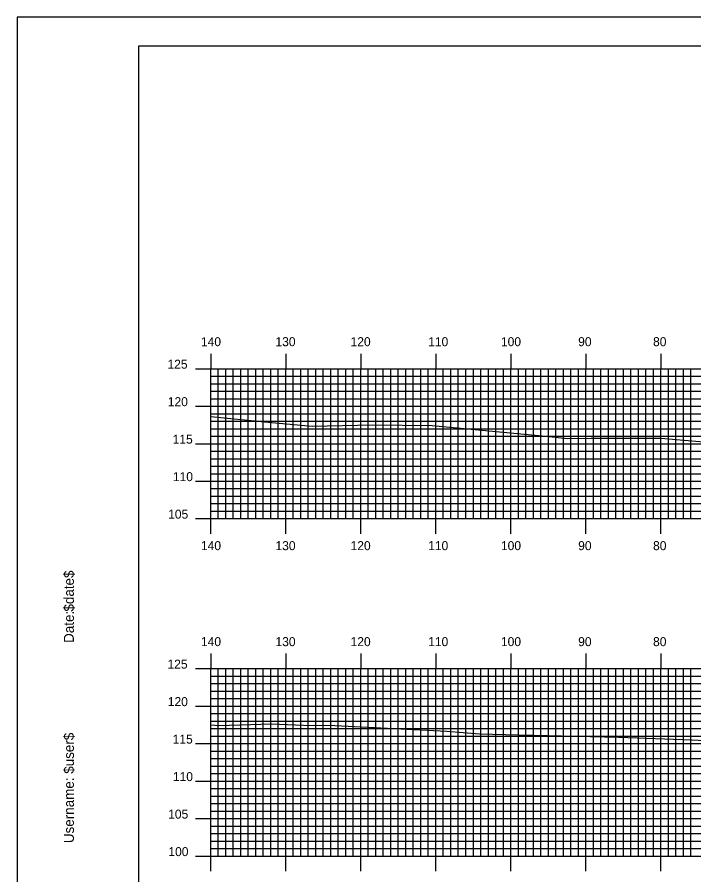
# Model space of a CAD drawing. Extents: x 1779893 to 1780236, y 442591 to 442811.
# Drawn here: x 1779892.6 to 1779982.7, y 442696.2 to 442810.5 of the extents above; entities that cross this region are included whole.
import ezdxf

# ---------------------------------------------------------------- set-up
doc = ezdxf.new("R2010")
doc.units = 0
for name, color, linetype in [('BORDER', 7, 'Continuous'), ('H_V ANNOTATION', 7, 'Continuous'), ('MAJOR', 7, 'Continuous'), ('MINOR', 7, 'Continuous'), ('PLOT BOUNDARY', 7, 'Continuous'), ('S_Roadway_Centerline', 7, 'Continuous')]:
    doc.layers.add(name, color=color, linetype=linetype)

msp = doc.modelspace()

# ---------------------------------------------------------------- linework, layer by layer
at = {"layer": 'BORDER'}
msp.add_lwpolyline([(1779908.76, 442596.67), (1780228.76, 442596.67), (1780228.76, 442806.67), (1779908.76, 442806.67)], close=True, dxfattribs=at)
at = {"layer": 'MAJOR'}
for p, q in [((1779918.36, 442765.67), (1779918.36, 442763.67)), ((1779928.36, 442765.67), (1779928.36, 442763.67)), ((1779938.36, 442765.67), (1779938.36, 442763.67)), ((1779948.36, 442765.67), (1779948.36, 442763.67)), ((1779958.36, 442765.67), (1779958.36, 442763.67)), ((1779968.36, 442765.67), (1779968.36, 442763.67)), ((1779978.36, 442765.67), (1779978.36, 442763.67)), ((1779916.35, 442763.67), (1779918.36, 442763.67)), ((1779918.36, 442763.67), (1780198.36, 442763.67)), ((1779918.36, 442743.67), (1779918.36, 442763.67)), ((1779918.36, 442743.67), (1779918.36, 442763.67)), ((1779918.36, 442763.67), (1780198.36, 442763.67)), ((1779928.36, 442743.67), (1779928.36, 442763.67)), ((1779938.36, 442743.67), (1779938.36, 442763.67)), ((1779948.36, 442743.67), (1779948.36, 442763.67)), ((1779958.36, 442743.67), (1779958.36, 442763.67)), ((1779968.36, 442743.67), (1779968.36, 442763.67)), ((1779978.36, 442743.67), (1779978.36, 442763.67)), ((1779916.35, 442758.67), (1779918.36, 442758.67)), ((1779918.36, 442758.67), (1780198.36, 442758.67)), ((1779916.35, 442753.67), (1779918.36, 442753.67)), ((1779918.36, 442753.67), (1780198.36, 442753.67)), ((1779916.35, 442748.67), (1779918.36, 442748.67)), ((1779918.36, 442748.67), (1780198.36, 442748.67)), ((1779916.35, 442743.67), (1779918.36, 442743.67)), ((1779918.36, 442743.67), (1780198.36, 442743.67)), ((1779918.36, 442743.67), (1780198.36, 442743.67)), ((1779918.36, 442741.66), (1779918.36, 442743.67)), ((1779928.36, 442741.66), (1779928.36, 442743.67)), ((1779938.36, 442741.66), (1779938.36, 442743.67)), ((1779948.36, 442741.66), (1779948.36, 442743.67)), ((1779958.36, 442741.66), (1779958.36, 442743.67)), ((1779968.36, 442741.66), (1779968.36, 442743.67)), ((1779978.36, 442741.66), (1779978.36, 442743.67)), ((1779918.36, 442725.67), (1779918.36, 442723.67)), ((1779928.36, 442725.67), (1779928.36, 442723.67)), ((1779938.36, 442725.67), (1779938.36, 442723.67)), ((1779948.36, 442725.67), (1779948.36, 442723.67)), ((1779958.36, 442725.67), (1779958.36, 442723.67)), ((1779968.36, 442725.67), (1779968.36, 442723.67)), ((1779978.36, 442725.67), (1779978.36, 442723.67)), ((1779916.35, 442723.67), (1779918.36, 442723.67)), ((1779918.36, 442723.67), (1780198.36, 442723.67)), ((1779918.36, 442698.67), (1779918.36, 442723.67)), ((1779918.36, 442698.67), (1779918.36, 442723.67)), ((1779918.36, 442723.67), (1780198.36, 442723.67)), ((1779928.36, 442698.67), (1779928.36, 442723.67)), ((1779938.36, 442698.67), (1779938.36, 442723.67)), ((1779948.36, 442698.67), (1779948.36, 442723.67)), ((1779958.36, 442698.67), (1779958.36, 442723.67)), ((1779968.36, 442698.67), (1779968.36, 442723.67)), ((1779978.36, 442698.67), (1779978.36, 442723.67)), ((1779916.35, 442718.67), (1779918.36, 442718.67)), ((1779918.36, 442718.67), (1780198.36, 442718.67)), ((1779916.35, 442713.67), (1779918.36, 442713.67)), ((1779918.36, 442713.67), (1780198.36, 442713.67)), ((1779916.35, 442708.67), (1779918.36, 442708.67)), ((1779918.36, 442708.67), (1780198.36, 442708.67)), ((1779916.35, 442703.67), (1779918.36, 442703.67)), ((1779918.36, 442703.67), (1780198.36, 442703.67)), ((1779916.35, 442698.67), (1779918.36, 442698.67)), ((1779918.36, 442698.67), (1780198.36, 442698.67)), ((1779918.36, 442698.67), (1780198.36, 442698.67)), ((1779918.36, 442696.66), (1779918.36, 442698.67)), ((1779928.36, 442696.66), (1779928.36, 442698.67)), ((1779938.36, 442696.66), (1779938.36, 442698.67)), ((1779948.36, 442696.66), (1779948.36, 442698.67)), ((1779958.36, 442696.66), (1779958.36, 442698.67)), ((1779968.36, 442696.66), (1779968.36, 442698.67)), ((1779978.36, 442696.66), (1779978.36, 442698.67))]:
    msp.add_line(p, q, dxfattribs=at)
at = {"layer": 'MINOR'}
for p, q in [((1779919.36, 442743.67), (1779919.36, 442763.67)), ((1779920.36, 442743.67), (1779920.36, 442763.67)), ((1779921.36, 442743.67), (1779921.36, 442763.67)), ((1779922.36, 442743.67), (1779922.36, 442763.67)), ((1779923.36, 442743.67), (1779923.36, 442763.67)), ((1779924.36, 442743.67), (1779924.36, 442763.67)), ((1779925.36, 442743.67), (1779925.36, 442763.67)), ((1779926.36, 442743.67), (1779926.36, 442763.67)), ((1779927.36, 442743.67), (1779927.36, 442763.67)), ((1779929.36, 442743.67), (1779929.36, 442763.67)), ((1779930.36, 442743.67), (1779930.36, 442763.67)), ((1779931.36, 442743.67), (1779931.36, 442763.67)), ((1779932.36, 442743.67), (1779932.36, 442763.67)), ((1779933.36, 442743.67), (1779933.36, 442763.67)), ((1779934.36, 442743.67), (1779934.36, 442763.67)), ((1779935.36, 442743.67), (1779935.36, 442763.67)), ((1779936.36, 442743.67), (1779936.36, 442763.67)), ((1779937.36, 442743.67), (1779937.36, 442763.67)), ((1779939.36, 442743.67), (1779939.36, 442763.67)), ((1779940.36, 442743.67), (1779940.36, 442763.67)), ((1779941.36, 442743.67), (1779941.36, 442763.67)), ((1779942.36, 442743.67), (1779942.36, 442763.67)), ((1779943.36, 442743.67), (1779943.36, 442763.67)), ((1779944.36, 442743.67), (1779944.36, 442763.67)), ((1779945.36, 442743.67), (1779945.36, 442763.67)), ((1779946.36, 442743.67), (1779946.36, 442763.67)), ((1779947.36, 442743.67), (1779947.36, 442763.67)), ((1779949.36, 442743.67), (1779949.36, 442763.67)), ((1779950.36, 442743.67), (1779950.36, 442763.67)), ((1779951.36, 442743.67), (1779951.36, 442763.67)), ((1779952.36, 442743.67), (1779952.36, 442763.67)), ((1779953.36, 442743.67), (1779953.36, 442763.67)), ((1779954.36, 442743.67), (1779954.36, 442763.67)), ((1779955.36, 442743.67), (1779955.36, 442763.67)), ((1779956.36, 442743.67), (1779956.36, 442763.67)), ((1779957.36, 442743.67), (1779957.36, 442763.67)), ((1779959.36, 442743.67), (1779959.36, 442763.67)), ((1779960.36, 442743.67), (1779960.36, 442763.67)), ((1779961.36, 442743.67), (1779961.36, 442763.67)), ((1779962.36, 442743.67), (1779962.36, 442763.67)), ((1779963.36, 442743.67), (1779963.36, 442763.67)), ((1779964.36, 442743.67), (1779964.36, 442763.67)), ((1779965.36, 442743.67), (1779965.36, 442763.67)), ((1779966.36, 442743.67), (1779966.36, 442763.67)), ((1779967.36, 442743.67), (1779967.36, 442763.67)), ((1779969.36, 442743.67), (1779969.36, 442763.67)), ((1779970.36, 442743.67), (1779970.36, 442763.67)), ((1779971.36, 442743.67), (1779971.36, 442763.67)), ((1779972.36, 442743.67), (1779972.36, 442763.67)), ((1779973.36, 442743.67), (1779973.36, 442763.67)), ((1779974.36, 442743.67), (1779974.36, 442763.67)), ((1779975.36, 442743.67), (1779975.36, 442763.67)), ((1779976.36, 442743.67), (1779976.36, 442763.67)), ((1779977.36, 442743.67), (1779977.36, 442763.67)), ((1779979.36, 442743.67), (1779979.36, 442763.67)), ((1779980.36, 442743.67), (1779980.36, 442763.67)), ((1779981.36, 442743.67), (1779981.36, 442763.67)), ((1779982.36, 442743.67), (1779982.36, 442763.67)), ((1779918.36, 442762.67), (1780198.36, 442762.67)), ((1779918.36, 442762.67), (1779920.36, 442762.67)), ((1779918.36, 442761.67), (1780198.36, 442761.67)), ((1779918.36, 442761.67), (1779920.36, 442761.67)), ((1779918.36, 442760.67), (1780198.36, 442760.67)), ((1779918.36, 442760.67), (1779920.36, 442760.67)), ((1779918.36, 442759.67), (1780198.36, 442759.67)), ((1779918.36, 442759.67), (1779920.36, 442759.67)), ((1779918.36, 442757.67), (1780198.36, 442757.67)), ((1779918.36, 442757.67), (1779920.36, 442757.67)), ((1779918.36, 442756.67), (1780198.36, 442756.67)), ((1779918.36, 442756.67), (1779920.36, 442756.67)), ((1779918.36, 442755.67), (1780198.36, 442755.67)), ((1779918.36, 442755.67), (1779920.36, 442755.67)), ((1779918.36, 442754.67), (1780198.36, 442754.67)), ((1779918.36, 442754.67), (1779920.36, 442754.67)), ((1779918.36, 442752.67), (1780198.36, 442752.67)), ((1779918.36, 442752.67), (1779920.36, 442752.67)), ((1779918.36, 442751.67), (1780198.36, 442751.67)), ((1779918.36, 442751.67), (1779920.36, 442751.67)), ((1779918.36, 442750.67), (1780198.36, 442750.67)), ((1779918.36, 442750.67), (1779920.36, 442750.67)), ((1779918.36, 442749.67), (1780198.36, 442749.67)), ((1779918.36, 442749.67), (1779920.36, 442749.67)), ((1779918.36, 442747.67), (1780198.36, 442747.67)), ((1779918.36, 442747.67), (1779920.36, 442747.67)), ((1779918.36, 442746.67), (1780198.36, 442746.67)), ((1779918.36, 442746.67), (1779920.36, 442746.67)), ((1779918.36, 442745.67), (1780198.36, 442745.67)), ((1779918.36, 442745.67), (1779920.36, 442745.67)), ((1779918.36, 442744.67), (1780198.36, 442744.67)), ((1779918.36, 442744.67), (1779920.36, 442744.67)), ((1779919.36, 442698.67), (1779919.36, 442723.67)), ((1779920.36, 442698.67), (1779920.36, 442723.67)), ((1779921.36, 442698.67), (1779921.36, 442723.67)), ((1779922.36, 442698.67), (1779922.36, 442723.67)), ((1779923.36, 442698.67), (1779923.36, 442723.67)), ((1779924.36, 442698.67), (1779924.36, 442723.67)), ((1779925.36, 442698.67), (1779925.36, 442723.67)), ((1779926.36, 442698.67), (1779926.36, 442723.67)), ((1779927.36, 442698.67), (1779927.36, 442723.67)), ((1779929.36, 442698.67), (1779929.36, 442723.67)), ((1779930.36, 442698.67), (1779930.36, 442723.67)), ((1779931.36, 442698.67), (1779931.36, 442723.67)), ((1779932.36, 442698.67), (1779932.36, 442723.67)), ((1779933.36, 442698.67), (1779933.36, 442723.67)), ((1779934.36, 442698.67), (1779934.36, 442723.67)), ((1779935.36, 442698.67), (1779935.36, 442723.67)), ((1779936.36, 442698.67), (1779936.36, 442723.67)), ((1779937.36, 442698.67), (1779937.36, 442723.67)), ((1779939.36, 442698.67), (1779939.36, 442723.67)), ((1779940.36, 442698.67), (1779940.36, 442723.67)), ((1779941.36, 442698.67), (1779941.36, 442723.67)), ((1779942.36, 442698.67), (1779942.36, 442723.67)), ((1779943.36, 442698.67), (1779943.36, 442723.67)), ((1779944.36, 442698.67), (1779944.36, 442723.67)), ((1779945.36, 442698.67), (1779945.36, 442723.67)), ((1779946.36, 442698.67), (1779946.36, 442723.67)), ((1779947.36, 442698.67), (1779947.36, 442723.67)), ((1779949.36, 442698.67), (1779949.36, 442723.67)), ((1779950.36, 442698.67), (1779950.36, 442723.67)), ((1779951.36, 442698.67), (1779951.36, 442723.67)), ((1779952.36, 442698.67), (1779952.36, 442723.67)), ((1779953.36, 442698.67), (1779953.36, 442723.67)), ((1779954.36, 442698.67), (1779954.36, 442723.67)), ((1779955.36, 442698.67), (1779955.36, 442723.67)), ((1779956.36, 442698.67), (1779956.36, 442723.67)), ((1779957.36, 442698.67), (1779957.36, 442723.67)), ((1779959.36, 442698.67), (1779959.36, 442723.67)), ((1779960.36, 442698.67), (1779960.36, 442723.67)), ((1779961.36, 442698.67), (1779961.36, 442723.67)), ((1779962.36, 442698.67), (1779962.36, 442723.67)), ((1779963.36, 442698.67), (1779963.36, 442723.67)), ((1779964.36, 442698.67), (1779964.36, 442723.67)), ((1779965.36, 442698.67), (1779965.36, 442723.67)), ((1779966.36, 442698.67), (1779966.36, 442723.67)), ((1779967.36, 442698.67), (1779967.36, 442723.67)), ((1779969.36, 442698.67), (1779969.36, 442723.67)), ((1779970.36, 442698.67), (1779970.36, 442723.67)), ((1779971.36, 442698.67), (1779971.36, 442723.67)), ((1779972.36, 442698.67), (1779972.36, 442723.67)), ((1779973.36, 442698.67), (1779973.36, 442723.67)), ((1779974.36, 442698.67), (1779974.36, 442723.67)), ((1779975.36, 442698.67), (1779975.36, 442723.67)), ((1779976.36, 442698.67), (1779976.36, 442723.67)), ((1779977.36, 442698.67), (1779977.36, 442723.67)), ((1779979.36, 442698.67), (1779979.36, 442723.67)), ((1779980.36, 442698.67), (1779980.36, 442723.67)), ((1779981.36, 442698.67), (1779981.36, 442723.67)), ((1779982.36, 442698.67), (1779982.36, 442723.67)), ((1779918.36, 442722.67), (1780198.36, 442722.67)), ((1779918.36, 442722.67), (1779920.36, 442722.67)), ((1779918.36, 442721.67), (1780198.36, 442721.67)), ((1779918.36, 442721.67), (1779920.36, 442721.67)), ((1779918.36, 442720.67), (1780198.36, 442720.67)), ((1779918.36, 442720.67), (1779920.36, 442720.67)), ((1779918.36, 442719.67), (1780198.36, 442719.67)), ((1779918.36, 442719.67), (1779920.36, 442719.67)), ((1779918.36, 442717.67), (1780198.36, 442717.67)), ((1779918.36, 442717.67), (1779920.36, 442717.67)), ((1779918.36, 442716.67), (1780198.36, 442716.67)), ((1779918.36, 442716.67), (1779920.36, 442716.67)), ((1779918.36, 442715.67), (1780198.36, 442715.67)), ((1779918.36, 442715.67), (1779920.36, 442715.67)), ((1779918.36, 442714.67), (1780198.36, 442714.67)), ((1779918.36, 442714.67), (1779920.36, 442714.67)), ((1779918.36, 442712.67), (1780198.36, 442712.67)), ((1779918.36, 442712.67), (1779920.36, 442712.67)), ((1779918.36, 442711.67), (1780198.36, 442711.67)), ((1779918.36, 442711.67), (1779920.36, 442711.67)), ((1779918.36, 442710.67), (1780198.36, 442710.67)), ((1779918.36, 442710.67), (1779920.36, 442710.67)), ((1779918.36, 442709.67), (1780198.36, 442709.67)), ((1779918.36, 442709.67), (1779920.36, 442709.67)), ((1779918.36, 442707.67), (1780198.36, 442707.67)), ((1779918.36, 442707.67), (1779920.36, 442707.67)), ((1779918.36, 442706.67), (1780198.36, 442706.67)), ((1779918.36, 442706.67), (1779920.36, 442706.67)), ((1779918.36, 442705.67), (1780198.36, 442705.67)), ((1779918.36, 442705.67), (1779920.36, 442705.67)), ((1779918.36, 442704.67), (1780198.36, 442704.67)), ((1779918.36, 442704.67), (1779920.36, 442704.67)), ((1779918.36, 442702.67), (1780198.36, 442702.67)), ((1779918.36, 442702.67), (1779920.36, 442702.67)), ((1779918.36, 442701.67), (1780198.36, 442701.67)), ((1779918.36, 442701.67), (1779920.36, 442701.67)), ((1779918.36, 442700.67), (1780198.36, 442700.67)), ((1779918.36, 442700.67), (1779920.36, 442700.67)), ((1779918.36, 442699.67), (1780198.36, 442699.67)), ((1779918.36, 442699.67), (1779920.36, 442699.67))]:
    msp.add_line(p, q, dxfattribs=at)
at = {"layer": 'PLOT BOUNDARY'}
msp.add_lwpolyline([(1779892.57, 442590.55), (1780232.57, 442590.55), (1780232.57, 442810.55), (1779892.57, 442810.55)], close=True, dxfattribs=at)
at = {"layer": 'S_Roadway_Centerline'}
for points in [[(1779918.36, 442757.28), (1779925.51, 442756.59), (1779931.89, 442755.99), (1779939.94, 442756.18), (1779947.89, 442756.09), (1779963, 442754.65), (1779965.9, 442754.38), (1779969.05, 442754.41), (1779978.36, 442754.4), (1779987.69, 442753.59)], [(1779918.36, 442716.16), (1779919.43, 442716.09), (1779926.44, 442716.3), (1779930.71, 442716.12), (1779934.92, 442716.07), (1779949.84, 442715.34), (1779954.18, 442714.99), (1779959.36, 442714.86), (1779972.75, 442714.53), (1779982.49, 442714.17), (1779988.63, 442713.86)]]:
    msp.add_lwpolyline(points, dxfattribs=at)

# ---------------------------------------------------------------- texts
at = {"layer": 'BORDER'}
for s, p in [('$date$', (1779900.13, 442731.28)), ('Date:', (1779900.13, 442727.1)), ('$user$', (1779900.13, 442709.65)), ('Username:', (1779900.13, 442700.4))]:
    msp.add_text(s, height=1.339, rotation=90, dxfattribs=at).set_placement(p)
at = {"layer": 'H_V ANNOTATION'}
for s, p in [('140', (1779917.06, 442766.67)), ('130', (1779926.99, 442766.67)), ('120', (1779937, 442766.67)), ('110', (1779947.34, 442766.67)), ('100', (1779957.04, 442766.67)), ('90', (1779967.33, 442766.67)), ('80', (1779977.31, 442766.67)), ('125', (1779912.6, 442763.67)), ('120', (1779912.64, 442758.67)), ('115', (1779913.29, 442753.67)), ('110', (1779913.32, 442748.67)), ('105', (1779912.69, 442743.67)), ('140', (1779917.06, 442739.47)), ('130', (1779926.99, 442739.47)), ('120', (1779937, 442739.47)), ('110', (1779947.34, 442739.47)), ('100', (1779957.04, 442739.47)), ('90', (1779967.33, 442739.47)), ('80', (1779977.31, 442739.47)), ('140', (1779917.06, 442726.67)), ('130', (1779926.99, 442726.67)), ('120', (1779937, 442726.67)), ('110', (1779947.34, 442726.67)), ('100', (1779957.04, 442726.67)), ('90', (1779967.33, 442726.67)), ('80', (1779977.31, 442726.67)), ('125', (1779912.6, 442723.67)), ('120', (1779912.64, 442718.67)), ('115', (1779913.29, 442713.67)), ('110', (1779913.32, 442708.67)), ('105', (1779912.69, 442703.67)), ('100', (1779912.72, 442698.67))]:
    msp.add_text(s, height=1.2, dxfattribs=at).set_placement(p)
at = {"layer": 'MAJOR'}
for p in [(1779918.35, 442743.67), (1779918.35, 442698.67)]:
    msp.add_text('-', height=0.012, dxfattribs=at).set_placement(p)

doc.saveas('drawing.dxf')
